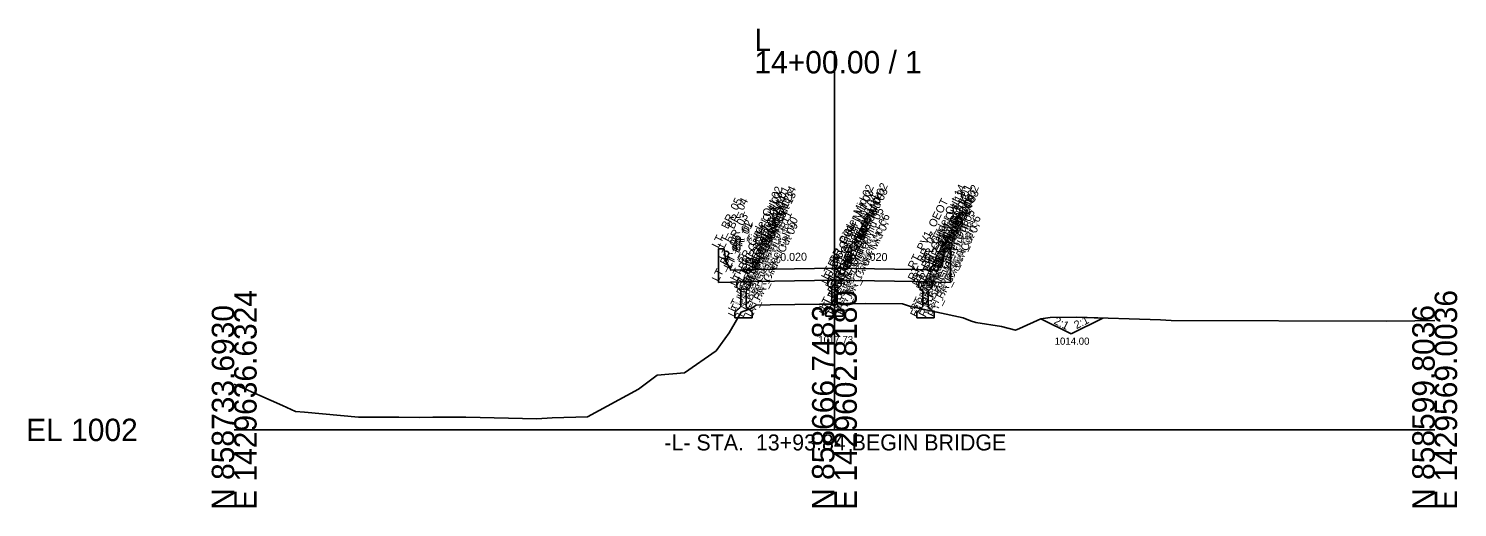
# Model space of a CAD drawing. Extents: x -26 to 153, y -10 to 13058.
# Drawn here: x -25.7 to 152.8, y 4990.3 to 5050.2 of the extents above; entities that cross this region are included whole.
import ezdxf

# ---------------------------------------------------------------- set-up
doc = ezdxf.new("R2010")
doc.units = 0
for name, color, linetype in [('Default', 7, 'Continuous'), ('Exist Cross Section Cell', 7, 'Continuous'), ('Exist XS Ground Line', 7, 'Continuous'), ('Old_Level_50', 7, 'Continuous'), ('Prop CMT Concrete Structures', 7, 'Continuous'), ('Prop CMT Ditch DDE', 7, 'Continuous'), ('Prop CMT Subgrade Daylight Point', 7, 'Continuous'), ('Prop XS Dump Level', 7, 'Continuous'), ('Prop XS SE Text', 7, 'Continuous'), ('Prop XS Side Slope Text', 7, 'Continuous'), ('Prop XSC Text', 7, 'Continuous')]:
    doc.layers.add(name, color=color, linetype=linetype)

msp = doc.modelspace()

# ---------------------------------------------------------------- linework, layer by layer
at = {"layer": 'Exist Cross Section Cell'}
for p, q in [((75, 5000), (75, 5047.36)), ((0, 5000), (75, 5000)), ((75, 5000), (150, 5000))]:
    msp.add_line(p, q, dxfattribs=at)
at = {"layer": 'Exist XS Ground Line'}
msp.add_lwpolyline([(0, 5005.73), (6.02, 5003.05), (7.64, 5002.3), (8.79, 5002.22), (15.53, 5001.6), (20.58, 5001.57), (23.13, 5001.56), (24.82, 5001.58), (28.93, 5001.59), (37.81, 5001.39), (39.72, 5001.51), (44.15, 5001.64), (50.51, 5005.07), (52.85, 5006.83), (56.25, 5007.14), (60.2, 5009.88), (61.83, 5012.15), (63.34, 5014.71), (64.6, 5015.17), (65.23, 5015.6), (66.95, 5015.62), (73.15, 5015.71), (75, 5015.73), (78.87, 5015.79), (83.49, 5015.75), (84.51, 5015.41), (91.07, 5013.99), (91.98, 5013.62), (92.66, 5013.43), (95.86, 5012.93), (97.63, 5012.48), (98.11, 5012.68), (100.8, 5013.88), (101.94, 5014.06), (105.28, 5014.08), (115.76, 5013.76), (117.06, 5013.69), (143.93, 5013.58), (147.53, 5013.65), (150, 5013.69)], dxfattribs=at)
at = {"layer": 'Old_Level_50'}
for p, q in [((100.8, 5013.88), (104.56, 5012)), ((104.56, 5012), (108.52, 5013.98)), ((108.52, 5013.98), (105.28, 5014.08))]:
    msp.add_line(p, q, dxfattribs=at)
msp.add_lwpolyline([(105.28, 5014.08), (101.94, 5014.06), (100.8, 5013.88)], dxfattribs=at)
at = {"layer": 'Prop CMT Concrete Structures'}
for points in [[(75, 5020.23), (65, 5020.03), (62, 5019.97), (61.99, 5020.22), (61.41, 5021.05), (61.24, 5022.63), (60.5, 5022.63), (60.5, 5018.44)], [(75, 5020.23), (85, 5020.03), (88, 5019.97), (88.01, 5020.22), (88.59, 5021.05), (88.76, 5022.63), (89.5, 5022.63), (89.5, 5018.44)], [(60.5, 5018.44), (65, 5018.53), (75, 5018.73)], [(75, 5018.73), (74.17, 5018.71)], [(74.17, 5018.71), (74.17, 5018.06)], [(75, 5018.73), (75, 5020.23)], [(75, 5018.73), (75, 5020.23)], [(75, 5014.23), (75, 5018.73)], [(75, 5018.73), (75.83, 5018.71)], [(75, 5014.23), (75, 5018.73)], [(89.5, 5018.44), (85, 5018.53), (75, 5018.73)], [(75.83, 5018.71), (75.83, 5018.06)], [(64.46, 5018.52), (63.62, 5018.5), (62.79, 5018.48)], [(62.79, 5018.48), (62.79, 5017.83)], [(62.79, 5017.83), (63.29, 5017.33)], [(63.29, 5017.33), (63.29, 5015.42)], [(63.96, 5017.33), (64.46, 5017.83)], [(63.96, 5015.42), (63.96, 5017.33)], [(64.46, 5017.83), (64.46, 5018.52)], [(74.17, 5018.06), (74.67, 5017.56)], [(74.67, 5017.56), (74.67, 5015.64)], [(75.83, 5018.06), (75.33, 5017.56)], [(75.33, 5017.56), (75.33, 5015.64)], [(85.54, 5018.52), (86.38, 5018.5), (87.21, 5018.48)], [(85.54, 5017.83), (85.54, 5018.52)], [(86.04, 5017.33), (85.54, 5017.83)], [(86.04, 5015.42), (86.04, 5017.33)], [(87.21, 5017.83), (86.71, 5017.33)], [(86.71, 5017.33), (86.71, 5015.42)], [(87.21, 5018.48), (87.21, 5017.83)], [(63.29, 5015.42), (62.54, 5014.67)], [(64.71, 5014.67), (63.96, 5015.42)], [(74.67, 5015.64), (73.92, 5014.89)], [(75.33, 5015.64), (76.08, 5014.89)], [(85.29, 5014.67), (86.04, 5015.42)], [(86.71, 5015.42), (87.46, 5014.67)], [(62.54, 5014.67), (62.54, 5014)], [(62.54, 5014), (63.62, 5014), (64.71, 5014)], [(64.71, 5014), (64.71, 5014.67)], [(73.92, 5014.89), (73.92, 5014.23)], [(73.92, 5014.23), (75, 5014.23)], [(76.08, 5014.23), (75, 5014.23)], [(76.08, 5014.89), (76.08, 5014.23)], [(85.29, 5014), (85.29, 5014.67)], [(87.46, 5014), (86.38, 5014), (85.29, 5014)], [(87.46, 5014.67), (87.46, 5014)]]:
    msp.add_lwpolyline(points, dxfattribs=at)
at = {"layer": 'Prop CMT Ditch DDE'}
for q in [(100.8, 5013.88), (108.52, 5013.98)]:
    msp.add_line((104.56, 5012), q, dxfattribs=at)

# ---------------------------------------------------------------- texts
at = {"layer": 'Default'}
for s, height, p in [('1014.00', 0.9, (102.51, 5010.64)), ('-', 0.0001, (0, 5000))]:
    msp.add_text(s, height=height, dxfattribs=at).set_placement(p)
at = {"layer": 'Exist Cross Section Cell'}
for s, p in [('L', (65, 5047.36)), ('14+00.00 / 1', (65, 5044.56)), ('EL 1002', (-26, 4998.6))]:
    msp.add_text(s, height=2.8, dxfattribs=at).set_placement(p)
for s, p in [('E 1429636.6324', (2.8, 4990)), ('E 1429602.8180', (77.8, 4990)), ('E 1429569.0036', (152.8, 4990)), ('N 858733.6930', (0, 4990)), ('N 858666.7483', (75, 4990)), ('N 858599.8036', (150, 4990))]:
    msp.add_text(s, height=2.8, rotation=90, dxfattribs=at).set_placement(p)
at = {"layer": 'Prop CMT Subgrade Daylight Point'}
msp.add_text('1017.73', height=0.9, dxfattribs=at).set_placement((72.98, 5010.83))
at = {"layer": 'Prop XS Dump Level'}
for s, p in [('LT_BR_Girder Out 02', (62.79, 5018.48)), ('LT_BR_Girder Out 03', (62.79, 5017.83)), ('LT_BR_Girder Out 04', (63.29, 5017.33)), ('LT_BR_Girder Out 01', (63.62, 5018.5)), ('LT_BR_Girder Out 12', (63.96, 5017.33)), ('LT_BR_Girder Out 14', (64.46, 5018.52)), ('LT_BR_Girder Out 13', (64.46, 5017.83)), ('LT_BR_Girder Mid 02', (74.17, 5018.71)), ('LT_BR_Girder Mid 03', (74.17, 5018.06)), ('LT_BR_Girder Mid 04', (74.67, 5017.56)), ('RT_BR_Girder Mid 04', (75.33, 5017.56)), ('RT_BR_Girder Mid 02', (75.83, 5018.71)), ('RT_BR_Girder Mid 03', (75.83, 5018.06)), ('RT_BR_Girder Out 14', (85.54, 5018.52)), ('RT_BR_Girder Out 13', (85.54, 5017.83)), ('RT_BR_Girder Out 12', (86.04, 5017.33)), ('RT_BR_Girder Out 01', (86.38, 5018.5)), ('RT_BR_Girder Out 04', (86.71, 5017.33)), ('RT_BR_Girder Out 02', (87.21, 5018.48)), ('RT_BR_Girder Out 03', (87.21, 5017.83)), ('LT_ BR_05', (60.5, 5022.63)), ('LT_ BR_04', (61.24, 5022.63)), ('LT_PV1_OEOT', (65, 5020.03)), ('LT_BR_Girder Mid 05', (74.67, 5015.64)), ('RT_BR_Girder Mid 05', (75.33, 5015.64)), ('RT_PV1_OEOT', (85, 5020.03)), ('RT_BR_Girder Out 05', (86.71, 5015.42)), ('RT_ BR_04', (88.76, 5022.63)), ('RT_ BR_05', (89.5, 5022.63)), ('LT_BR_03', (61.41, 5021.05)), ('LT_BR_02', (61.99, 5020.22)), ('LT_BR_01', (62, 5019.97)), ('LT_BR_Girder Out 06', (62.54, 5014.67)), ('LT_BR_Girder Out 07', (62.54, 5014)), ('LT_BR_Girder Out 05', (63.29, 5015.42)), ('LT_BR_Girder Out 08', (63.62, 5014)), ('LT_BR_Girder Out 11', (63.96, 5015.42)), ('LT_BR_Girder Out 10', (64.71, 5014.67)), ('LT_BR_Girder Out 09', (64.71, 5014)), ('LT_BR_Girder Mid 06', (73.92, 5014.89)), ('LT_BR_Girder Mid 07', (73.92, 5014.23)), ('RT_BR_Girder Mid 06', (76.08, 5014.89)), ('RT_BR_Girder Mid 07', (76.08, 5014.23)), ('RT_BR_Girder Out 10', (85.29, 5014.67)), ('RT_BR_Girder Out 09', (85.29, 5014)), ('RT_BR_Girder Out 11', (86.04, 5015.42)), ('RT_BR_Girder Out 08', (86.38, 5014)), ('RT_BR_Girder Out 06', (87.46, 5014.67)), ('RT_BR_Girder Out 07', (87.46, 5014)), ('RT_BR_01', (88, 5019.97)), ('RT_BR_02', (88.01, 5020.22)), ('RT_BR_03', (88.59, 5021.05)), ('LT_BR_06', (60.5, 5018.44)), ('LT_BR_07', (65, 5018.53)), ('PV1_PGL', (75, 5020.23)), ('BR_Girder Mid 08', (75, 5014.23)), ('RT_BR_07', (85, 5018.53)), ('RT_BR_06', (89.5, 5018.44)), ('BR_PGL', (75, 5018.73))]:
    msp.add_text(s, height=1, rotation=63.5833, dxfattribs=at).set_placement(p)
at = {"layer": 'Prop XS SE Text'}
for rotation, p in [(1.1458, (68.23, 5021.09)), (358.8542, (78.27, 5021.16))]:
    msp.add_text('0.020', height=1, rotation=rotation, dxfattribs=at).set_placement(p)
at = {"layer": 'Prop XS Side Slope Text'}
for rotation, p in [(333.4349, (102.33, 5013.31)), (26.5651, (105.24, 5012.58))]:
    msp.add_text('2:1', height=1, rotation=rotation, dxfattribs=at).set_placement(p)
at = {"layer": 'Prop XSC Text'}
msp.add_text('-L- STA.  13+93.84 BEGIN BRIDGE', height=2, dxfattribs=at).set_placement((53.74, 4997.43))

doc.saveas('drawing.dxf')
